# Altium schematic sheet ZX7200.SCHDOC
size 762 x 279 mm; PageSetup: Record=PageOptions|SelectedOnly=False|CenterHorizontal=True|CenterVertical=True|PrintScale=0.95|XCorrection=1.00|YCorrection=1.00|PrintKind=1|BorderSize=5000000|LeftOffset=0|BottomOffset=0|Orientation=1|PaperLength=1000|PaperWidth=1000|Scale=100|PaperSource=7|PrintQuality=-4|MediaType=1|DitherType=10|PaperKind=A4|PrintScaleMode=0
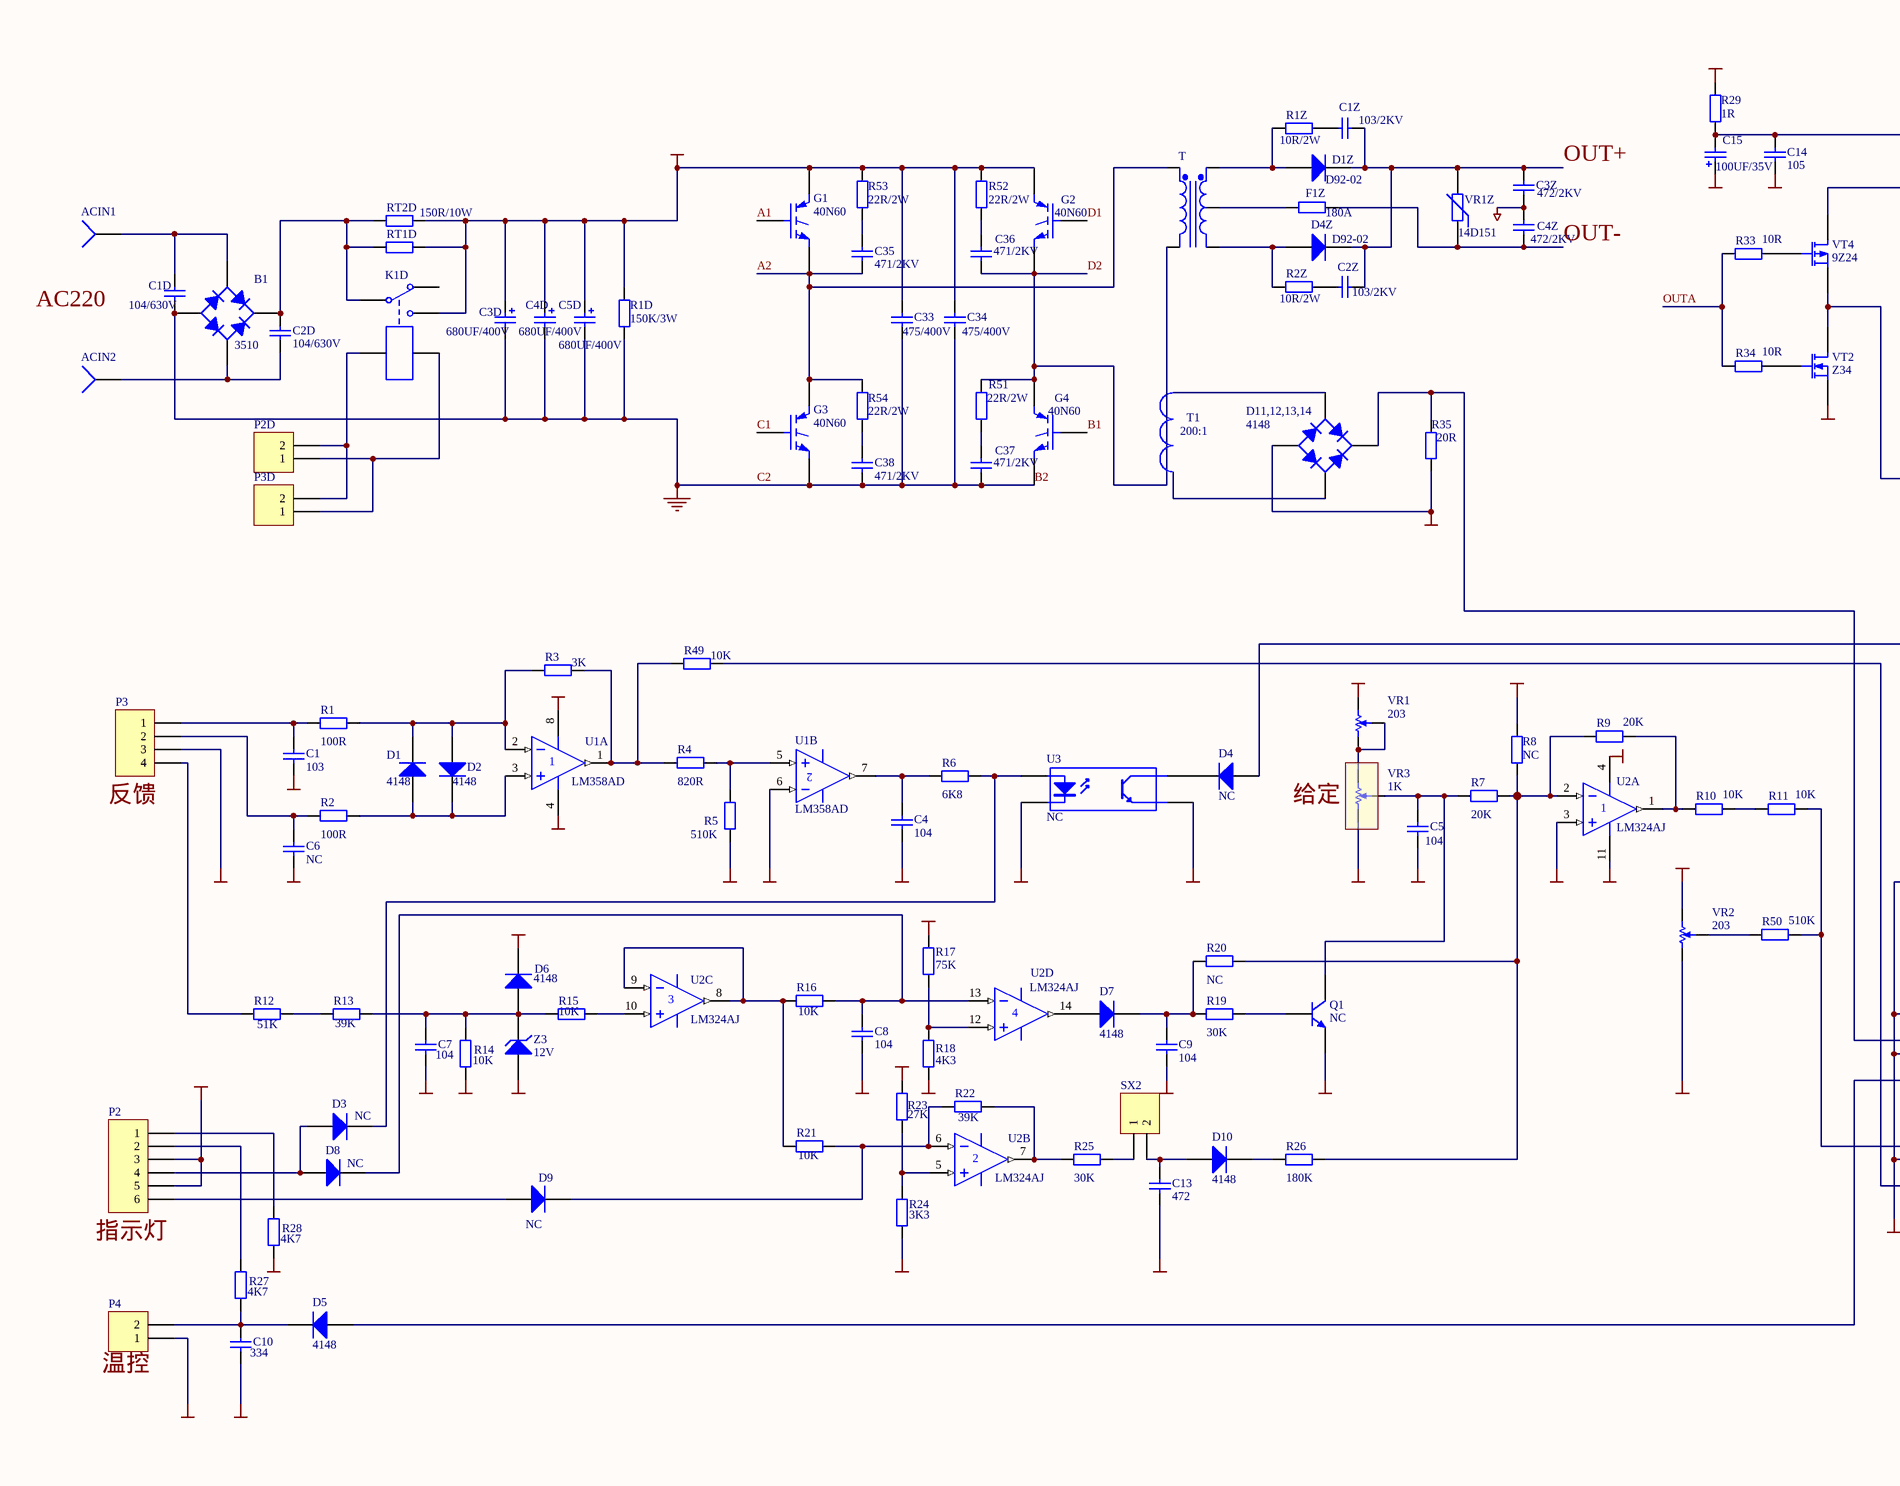
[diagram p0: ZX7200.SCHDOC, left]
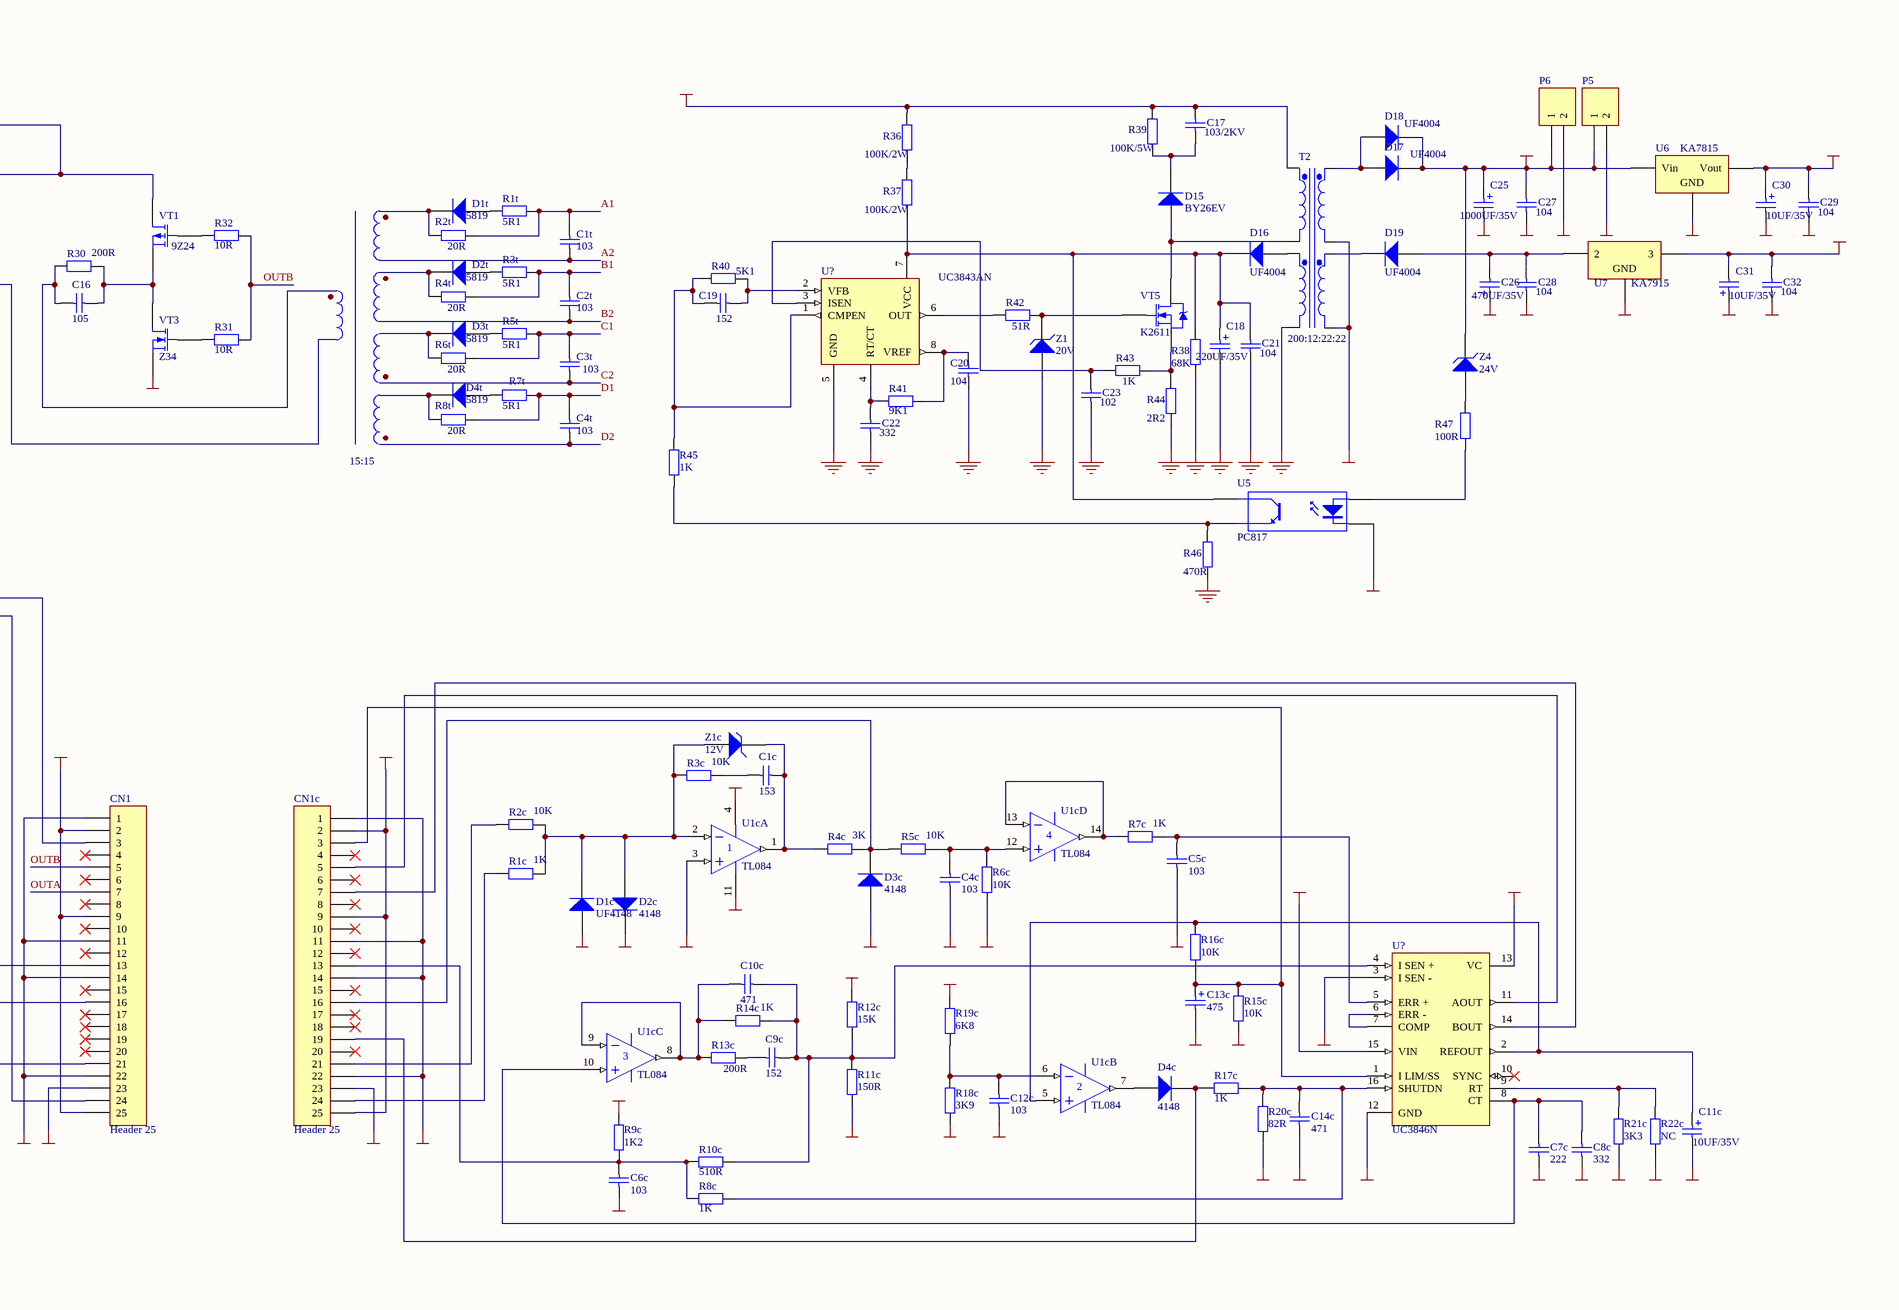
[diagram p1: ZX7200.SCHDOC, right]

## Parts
(Parts that share a designator on the sheet are numbered #1, #2 ... from top to bottom, then left to right.)
ACIN1  (no value)  [PIN1]
ACIN2  (no value)  [PIN1]
B1  3510  [E-BIP-P4/D10]
C1  103  [RAD-0.3]
C1c  153  [RAD-0.3]
C1D  104/630V  [RAD-0.3]
C1t  103  [RAD-0.3]
C1Z  103/2KV  [RAD-0.3]
C2D  104/630V  [RAD-0.3]
C2t  103  [RAD-0.3]
C2Z  103/2KV  [RAD-0.3]
C3D  680UF/400V  [POLAR0.8]
C3t  103  [RAD-0.3]
C3Z  472/2KV  [RAD-0.3]
C4  104  [RAD-0.3]
C4c  103  [RAD-0.3]
C4D  680UF/400V  [POLAR0.8]
C4t  103  [RAD-0.3]
C4Z  472/2KV  [RAD-0.3]
C5  104  [RAD-0.3]
C5c  103  [RAD-0.3]
C5D  680UF/400V  [POLAR0.8]
C6  NC  [RAD-0.3]
C6c  103  [RAD-0.3]
C7  104  [RAD-0.3]
C7c  222  [RAD-0.3]
C8  104  [RAD-0.3]
C8c  332  [RAD-0.3]
C9  104  [RAD-0.3]
C9c  152  [RAD-0.3]
C10  334  [RAD-0.3]
C10c  471  [RAD-0.3]
C11c  10UF/35V  [POLAR0.8]
C12c  103  [RAD-0.3]
C13  472  [RAD-0.3]
C13c  475  [POLAR0.8]
C14  105  [RAD-0.3]
C14c  471  [RAD-0.3]
C15  100UF/35V  [POLAR0.8]
C16  105  [RAD-0.3]
C17  103/2KV  [RAD-0.3]
C18  220UF/35V  [POLAR0.8]
C19  152  [RAD-0.3]
C20  104  [RAD-0.3]
C21  104  [RAD-0.3]
C22  332  [RAD-0.3]
C23  102  [RAD-0.3]
C25  1000UF/35V  [POLAR0.8]
C26  470UF/35V  [POLAR0.8]
C27  104  [RAD-0.3]
C28  104  [RAD-0.3]
C29  104  [RAD-0.3]
C30  10UF/35V  [POLAR0.8]
C31  10UF/35V  [POLAR0.8]
C32  104  [RAD-0.3]
C33  475/400V  [RAD-0.3]
C34  475/400V  [RAD-0.3]
C35  471/2KV  [RAD-0.3]
C36  471/2KV  [RAD-0.3]
C37  471/2KV  [RAD-0.3]
C38  471/2KV  [RAD-0.3]
CN1  Header 25  [HDR1X25]
CN1c  Header 25  [HDR1X25]
D1  4148  [DIO18.84-9.6x5.6]
D1c  UF4148  [DIO18.84-9.6x5.6]
D1t  5819  [DIO18.84-9.6x5.6]
D1Z  D92-02  [DIO18.84-9.6x5.6]
D2  4148  [DIO18.84-9.6x5.6]
D2c  4148  [DIO18.84-9.6x5.6]
D2t  5819  [DIO18.84-9.6x5.6]
D3  NC  [DIO18.84-9.6x5.6]
D3c  4148  [DIO18.84-9.6x5.6]
D3t  5819  [DIO18.84-9.6x5.6]
D4  NC  [DIO18.84-9.6x5.6]
D4c  4148  [DIO18.84-9.6x5.6]
D4t  5819  [DIO18.84-9.6x5.6]
D4Z  D92-02  [DIO18.84-9.6x5.6]
D5  4148  [DIO18.84-9.6x5.6]
D6  4148  [DIO18.84-9.6x5.6]
D7  4148  [DIO18.84-9.6x5.6]
D8  NC  [DIO18.84-9.6x5.6]
D9  NC  [DIO18.84-9.6x5.6]
D10  4148  [DIO18.84-9.6x5.6]
D11,12,13,14  4148  [E-BIP-P4/D10]
D15  BY26EV  [DIO18.84-9.6x5.6]
D16  UF4004  [DIO18.84-9.6x5.6]
D17  UF4004  [DIO18.84-9.6x5.6]
D18  UF4004  [DIO18.84-9.6x5.6]
D19  UF4004  [DIO18.84-9.6x5.6]
F1Z  180A  [AXIAL-0.4]
G1  40N60  [SFM-F3/Y2.3]
G2  40N60  [SFM-F3/Y2.3]
G3  40N60  [SFM-F3/Y2.3]
G4  40N60  [SFM-F3/Y2.3]
K1D  (no value)  [DIP-P5/X1.65]
P2  (no value)  [HDR1X6H]
P2D  (no value)  [HDR1X2]
P3  (no value)  [HDR1X4]
P3D  (no value)  [HDR1X2]
P4  (no value)  [HDR1X2]
P5  (no value)  [HDR1X2]
P6  (no value)  [HDR1X2]
Q1  NC  [BCY-W3/E4]
R1  100R  [AXIAL-0.4]
R1c  1K  [AXIAL-0.4]
R1D  150K/3W  [AXIAL-0.4]
R1t  5R1  [AXIAL-0.4]
R1Z  10R/2W  [AXIAL-0.4]
R2  100R  [AXIAL-0.4]
R2c  10K  [AXIAL-0.4]
R2t  20R  [AXIAL-0.4]
R2Z  10R/2W  [AXIAL-0.4]
R3  3K  [AXIAL-0.4]
R3c  10K  [AXIAL-0.4]
R3t  5R1  [AXIAL-0.4]
R4  820R  [AXIAL-0.4]
R4c  3K  [AXIAL-0.4]
R4t  20R  [AXIAL-0.4]
R5  510K  [AXIAL-0.4]
R5c  10K  [AXIAL-0.4]
R5t  5R1  [AXIAL-0.4]
R6  6K8  [AXIAL-0.4]
R6c  10K  [AXIAL-0.4]
R6t  20R  [AXIAL-0.4]
R7  20K  [AXIAL-0.4]
R7c  1K  [AXIAL-0.4]
R7t  5R1  [AXIAL-0.4]
R8  NC  [AXIAL-0.4]
R8c  1K  [AXIAL-0.4]
R8t  20R  [AXIAL-0.4]
R9  20K  [AXIAL-0.4]
R9c  1K2  [AXIAL-0.4]
R10  10K  [AXIAL-0.4]
R10c  510R  [AXIAL-0.4]
R11  10K  [AXIAL-0.4]
R11c  150R  [AXIAL-0.4]
R12  51K  [AXIAL-0.4]
R12c  15K  [AXIAL-0.4]
R13  39K  [AXIAL-0.4]
R13c  200R  [AXIAL-0.4]
R14  10K  [AXIAL-0.4]
R14c  1K  [AXIAL-0.4]
R15  10K  [AXIAL-0.4]
R15c  10K  [AXIAL-0.4]
R16  10K  [AXIAL-0.4]
R16c  10K  [AXIAL-0.4]
R17  75K  [AXIAL-0.4]
R17c  1K  [AXIAL-0.4]
R18  4K3  [AXIAL-0.4]
R18c  3K9  [AXIAL-0.4]
R19  30K  [AXIAL-0.4]
R19c  6K8  [AXIAL-0.4]
R20  NC  [AXIAL-0.4]
R20c  82R  [AXIAL-0.4]
R21  10K  [AXIAL-0.4]
R21c  3K3  [AXIAL-0.4]
R22  39K  [AXIAL-0.4]
R22c  NC  [AXIAL-0.4]
R23  27K  [AXIAL-0.4]
R24  3K3  [AXIAL-0.4]
R25  30K  [AXIAL-0.4]
R26  180K  [AXIAL-0.4]
R27  4K7  [AXIAL-0.4]
R28  4K7  [AXIAL-0.4]
R29  1R  [AXIAL-0.4]
R30  200R  [AXIAL-0.4]
R31  10R  [AXIAL-0.4]
R32  10R  [AXIAL-0.4]
R33  10R  [AXIAL-0.4]
R34  10R  [AXIAL-0.4]
R35  20R  [AXIAL-0.4]
R36  100K/2W  [AXIAL-0.4]
R37  100K/2W  [AXIAL-0.4]
R38  68K  [AXIAL-0.4]
R39  100K/5W  [AXIAL-0.4]
R40  5K1  [AXIAL-0.4]
R41  9K1  [AXIAL-0.4]
R42  51R  [AXIAL-0.4]
R43  1K  [AXIAL-0.4]
R44  2R2  [AXIAL-0.4]
R45  1K  [AXIAL-0.4]
R46  470R  [AXIAL-0.4]
R47  100R  [AXIAL-0.4]
R49  10K  [AXIAL-0.4]
R50  510K  [AXIAL-0.4]
R51  22R/2W  [AXIAL-0.4]
R52  22R/2W  [AXIAL-0.4]
R53  22R/2W  [AXIAL-0.4]
R54  22R/2W  [AXIAL-0.4]
RT1D  (no value)  [AXIAL-0.4]
RT2D  150R/10W  [AXIAL-0.4]
SX2  (no value)  [HDR1X2]
T  (no value)  [TRF_5]
T2  200:12:22:22  [TRF_8]
U1  LM358AD  [D008]  (parts A,B of 2)
U1c  TL084  [J014]  (parts A,B,C,D of 4)
U2  LM324AJ  [J014]  (parts A,B,C,D of 4)
U3  NC  [DIP-4]
U5  PC817  [DIP-4]
U6  KA7815  [SIP-G3/Y2]
U7  KA7915  [SIP-G3/Y2]
U?#1  UC3843AN  [626-05]
U?#2  UC3846N  [N016]
VR1  203  [POT4MM-2]
VR1Z  14D151  [R2012-0805]
VR2  203  [POT4MM-2]
VR3  1K  [POT4MM-2]
VT1  9Z24  [BCY-W3/B.8]
VT2  Z34  [BCY-W3/B.8]
VT3  Z34  [BCY-W3/B.8]
VT4  9Z24  [BCY-W3/B.8]
VT5  K2611  [SFM-T3/A4.7V]
Z1  20V  [DIODE-0.7]
Z1c  12V  [DIODE-0.7]
Z3  12V  [DIODE-0.7]
Z4  24V  [DIODE-0.7]

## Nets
+15V: C29.2 C30.1 CN1.2 CN1.9 CN1.25 CN1c.2 CN1c.9 CN1c.25 D6.2(K) P2.3 P2.5 R8.2 R9c.1 R17.1 R19c.2 R23.1 R29.2 U1.8(V+) U1c.4(V+) U2.4(V+) U6.3(Vout) U?#2.13(VC) U?#2.15(VIN) VR1.CW(+)
+24V: C25.1 C27.2 D17.2(K) D18.2(K) P5.1 P6.1 U6.1(Vin) Z4.2(K)
+310V: C3D.1 C4D.1 C5D.1 C17.2 C33.2 C34.2 G1.2(C) G2.2(C) K1D.3 R1D.2 R36.1 R39.1 R52.2 R53.2 RT1D.2 RT2D.2 T2.1(Pri1+)
-15V: C31.2 C32.2 CN1.23 CN1c.23 R5.2 R12c.2 U1.4(V-) U1c.11(V-) U2.11(V-) U7.3 VR2.CW(+)
B2: B1.1(A) C1D.1 C2t.1 C3D.2 C3t.1 C3Z.2 C4D.2 C4Z.1 C5D.2 C18.2 C20.1 C21.1 C22.1 C23.1 C33.1 C34.1 C37.1 C38.1 G3.3(E) G4.3(E) R1D.1 R38.2 R44.2 R46.2 T2.4(Pri2-) U?#1.5(GND) Z1.1(A)  [also labelled C2, GND]
NetC1_1: C1.1 C4.1 C4c.2 C5.2 C5c.2 C6.1 C6c.2 C7.1 C7c.2 C8.1 C8c.2 C9.2 C10.1 C11c.2 C12c.2 C13.2 C13c.2 C14.2 C14c.2 C15.1 C25.2 C26.1 C27.1 C28.1 C29.1 C30.2 C31.1 C32.1 CN1.1 CN1.11 CN1.14 CN1.22 CN1c.1 CN1c.11 CN1c.14 CN1c.22 D1c.1(A) D2c.2(K) D3c.1(A) D11,12,13,14.1(A) P3.3 P4.1 P5.2 P6.2 Q1.1(E) R6c.1 R11c.1 R14.2 R15c.2 R18.2 R18c.1 R20c.2 R21c.2 R22c.2 R24.2 R28.2 R35.1 T2.6(Sec1-) T2.8(Sec2-) U1.6(IN-) U1c.3(IN+) U2.3(IN+) U3.2(K) U3.4(E) U5.2(K) U6.2(GND) U7.2 U?#2.3(I_SEN_-) U?#2.12(GND) VR2.CCW(-) VR3.CCW(-) VT2.3(S) VT3.3(S) Z3.1(A)
A1: C1t.2 G1.1(G) R1t.2 R2t.2
A2: C1t.1 C35.1 G1.3(E) G3.2(C) R54.2 T.1(Pri+)
B1: C2t.2 G4.1(G) R3t.2 R4t.2
C1: C3t.2 G3.1(G) R5t.2 R6t.2
D1: C4t.2 G2.1(G) R7t.2 R8t.2
D2: C4t.1 C36.1 G2.3(E) G4.2(C) R51.2 T.2(Pri-)
OUT+: C1Z.1 C2Z.1 C3Z.1 D1Z.2(K) D4Z.2(K) VR1Z.2
OUT-: C4Z.2 F1Z.1 VR1Z.1
OUTA: CN1.7 R33.1 R34.1
OUTB: CN1.5 R31.1 R32.1
NetACIN1_1: ACIN1.1 B1.2(C) C1D.2
NetACIN2_1: ACIN2.1 B1.4(C) C2D.1
NetB1_3: B1.3(K) C2D.2 K1D.1 RT1D.1 RT2D.1
NetC1_2: C1.2 P3.1 R1.2
NetC1c_1: C1c.1 R4c.1 U1c.1(OUT) Z1c.2(K)
NetC1c_2: C1c.2 R3c.2
NetC1Z_2: C1Z.2 R1Z.1
NetC2Z_2: C2Z.2 R2Z.1
NetC4_2: C4.2 R6.1 U1.7(OUT)
NetC4c_1: C4c.1 R5c.2 R6c.2 U1c.12(IN+)
NetC5_1: C5.1 Q1.3(C) R7.1 VR3.W
NetC5c_1: C5c.1 R7c.2 U?#2.5(ERR_+)
NetC6_2: C6.2 P3.2 R2.2
NetC6c_1: C6c.1 CN1c.13 R8c.2 R9c.2 R10c.2
NetC7_2: C7.2 D6.1(A) R13.1 R14.1 R15.2 Z3.2(K)
NetC7c_1: C7c.1 C8c.1 U1c.10(IN+) U?#2.8(CT)
NetC8_2: C8.2 D8.2(K) R16.1 U2.13(IN-)
NetC9_1: C9.1 D7.2(K) R19.1 R20.1
NetC9c_1: C9c.1 R13c.2
NetC9c_2: C9c.2 C10c.2 R10c.1 R11c.2 R12c.1 R14c.2 U?#2.4(I_SEN_+)
NetC10_2: C10.2 D5.2(K) P4.2 R27.2
NetC10c_1: C10c.1 R13c.1 R14c.1 U1c.8(OUT) U1c.9(IN-)
NetC11c_1: C11c.1 R16c.2 U1c.5(IN+) U?#2.2(REFOUT)
NetC12c_1: C12c.1 R18c.2 R19c.1 U1c.6(IN-)
NetC13_1: C13.1 D10.1(A) SX2.2
NetC13c_1: C13c.1 CN1c.3 R15c.1 R16c.1 U?#2.1(I_LIM/SS)
NetC14_1: C14.1 C15.2 R29.1 VT1.1(D) VT4.1(D)
NetC14c_1: C14c.1 R8c.1 R17c.1 R20c.1 U?#2.16(SHUTDN)
NetC16_1: C16.1 R30.1
NetC16_2: C16.2 R30.2 VT1.3(S) VT3.1(D)
NetC17_1: C17.1 D15.2(K) R39.2
NetC18_1: C18.1 C21.2 D16.2(K) R37.2 R38.1 U5.3(C) U?#1.7(VCC)
NetC19_1: C19.1 R40.2 U?#1.2(VFB)
NetC19_2: C19.2 R40.1 R45.2 U?#1.1(CMPEN)
NetC20_2: C20.2 R41.1 U?#1.8(VREF)
NetC22_2: C22.2 R41.2 U?#1.4(RT/CT)
NetC23_2: C23.2 R43.1 U?#1.3(ISEN)
NetC26_2: C26.2 C28.2 D19.1(A) U7.1(2)
NetC35_2: C35.2 R53.1
NetC36_2: C36.2 R52.1
NetC37_2: C37.2 R51.1
NetC38_2: C38.2 R54.1
NetCN1_3: CN1.3 D4.1(A)
NetCN1_13: CN1.13 D11,12,13,14.3(K) R35.2
NetCN1_16: CN1.16 D5.1(A)
NetCN1_21: CN1.21 R11.2 R50.2
NetCN1_24: CN1.24 R49.1
NetCN1c_5: CN1c.5 U?#2.11(AOUT)
NetCN1c_7: CN1c.7 U?#2.14(BOUT)
NetCN1c_16: CN1c.16 D3c.2(K) R4c.2 R5c.1
NetCN1c_19: CN1c.19 D4c.2(K) R17c.2
NetCN1c_21: CN1c.21 R2c.1
NetCN1c_24: CN1c.24 R1c.1
NetD1_1: D1.1(A) D2.2(K) R2.1 U1.3(IN+)
NetD1_2: D1.2(K) D2.1(A) R1.1 R3.2 U1.2(IN-)
NetD1c_2: D1c.2(K) D2c.1(A) R1c.2 R2c.2 R3c.1 U1c.2(IN-) Z1c.1(A)
NetD1t_1: D1t.1(A) R1t.1
NetD1t_2: D1t.2(K) R2t.1
NetD1Z_1: D1Z.1(A) R1Z.2 T.3(Sec+)
NetD2t_1: D2t.1(A) R3t.1
NetD2t_2: D2t.2(K) R4t.1
NetD3_1: D3.1(A) D8.1(A) P2.4
NetD3_2: D3.2(K) R6.2 U3.1(A)
NetD3t_1: D3t.1(A) R5t.1
NetD3t_2: D3t.2(K) R6t.1
NetD4_2: D4.2(K) U3.3(C)
NetD4c_1: D4c.1(A) U1c.7(OUT)
NetD4t_1: D4t.1(A) R7t.1
NetD4t_2: D4t.2(K) R8t.1
NetD4Z_1: D4Z.1(A) R2Z.2 T.5(Sec-)
NetD7_1: D7.1(A) U2.14(OUT)
NetD9_1: D9.1(A) P2.6
NetD9_2: D9.2(K) R21.1 R22.2 U2.6(IN-)
NetD10_2: D10.2(K) R26.1
NetD15_1: D15.1(A) T2.2(Pri1-) VT5.2(D)
NetD16_1: D16.1(A) T2.3(Pri2+)
NetD17_1: D17.1(A) D18.1(A) T2.5(Sec1+)
NetD19_2: D19.2(K) T2.7(Sec2+)
NetF1Z_2: F1Z.2 T.4(SecCT)
NetK1D_4: K1D.4 P2D.2 P3D.2
NetK1D_5: K1D.5 P2D.1 P3D.1
NetP2_1: P2.1 R28.1
NetP2_2: P2.2 R27.1
NetP3_4: P3.4 R12.2
NetQ1_2: Q1.2(B) R19.2
NetR3_1: R3.1 R4.2 R49.2 U1.1(OUT)
NetR4_1: R4.1 R5.1 U1.5(IN+)
NetR7_2: R7.2 R8.1 R9.1 R20.2 R26.2 U2.2(IN-)
NetR7c_1: R7c.1 U1c.13(IN-) U1c.14(OUT)
NetR9_2: R9.2 R10.1 U2.1(OUT)
NetR10_2: R10.2 R11.1
NetR12_1: R12.1 R13.2
NetR15_1: R15.1 U2.10(IN+)
NetR16_2: R16.2 R21.2 U2.8(OUT) U2.9(IN-)
NetR17_2: R17.2 R18.1 U2.12(IN+)
NetR21c_1: R21c.1 R22c.1 U?#2.9(RT)
NetR22_1: R22.1 R25.1 U2.7(OUT)
NetR23_2: R23.2 R24.1 U2.5(IN+)
NetR25_2: R25.2 SX2.1
NetR31_2: R31.2 VT3.2(G)
NetR32_2: R32.2 VT1.2(G)
NetR33_2: R33.2 VT4.2(G)
NetR34_2: R34.2 VT2.2(G)
NetR36_2: R36.2 R37.1
NetR42_1: R42.1 U?#1.6(OUT)
NetR42_2: R42.2 VT5.1(G) Z1.2(K)
NetR43_2: R43.2 R44.1 VT5.3(S)
NetR45_1: R45.1 R46.1 U5.4(E)
NetR47_1: R47.1 Z4.1(A)
NetR47_2: R47.2 U5.1(A)
NetR50_1: R50.1 VR2.W
NetU?#2_6: U?#2.6(ERR_-) U?#2.7(COMP)
NetVR1_CCW: VR1.CCW(-) VR1.W VR3.CW(+)
NetVT2_1: VT2.1(D) VT4.3(S)

Not connected (* = marked no-connect by the designer): CN1 4* 6* 8* 10* 12* 15* 17* 18* 19* 20*; CN1c 4* 6* 8* 10* 12* 15* 17* 18* 20*; D11,12,13,14 2(C) 4(C); K1D 2; U?#2 10(SYNC)*

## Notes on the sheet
- AC220
- 200:1
- T1
- 15:15
- (near P3) 反馈
- 给定
- (near P2) 指示灯
- (near P4) 温控

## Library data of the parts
ACIN1 ACIN2 = Socket
B1 D11,12,13,14 = Bridge1: Full Wave Diode Bridge
C1 C1c C1D C1t C1Z C2D C2t C2Z C3t C3Z C4 C4c C4t C4Z C5 C5c C6 C6c C7 C7c C8 C8c C9 C9c C10 C10c C12c C13 C14 C14c C16 C17 C19-C23 C27-C29 C32-C38 = Cap: Capacitor; Value: 100pF
C3D C4D C5D C11c C13c C15 C18 C25 C26 C30 C31 = Cap Pol2: Polarized Capacitor (Axial); Value: 100pF
CN1 CN1c = Header 25: Header, 25-Pin
D1 D1c D1t D1Z D2 D2c D2t D3 D3c D3t D4 D4c D4t D4Z D5-D10 D15-D19 = Diode 1N5401: 3 Amp General Purpose Rectifier
F1Z R1 R1D R1t R1Z R2 R2c R2t R2Z R3 R3c R3t R4 R4c R4t R5 R5c R5t R6 R6c R6t R7 R7t R8 R8t R9 R9c R10 R10c R11 R11c R12 R12c R13 R13c R14 R15 R15c R16 R16c R17 R18 R18c R19 R19c R20 R20c R21 R21c R22 R22c R23-R42 R44 R46 R47 R49-R54 RT1D RT2D = Res2: Resistor; Value: 1K
G1-G4 = IGBT-N: Insulated Gate Bipolar Transistor (N-Channel)
K1D = Relay-SPDT: Single-Pole Dual-Throw Relay
P2 = Header 6H: Header, 6-Pin, Right Angle
P2D P3D P4-P6 SX2 = Header 2: Header, 2-Pin
P3 = Header 4: Header, 4-Pin
Q1 = 2N3904: NPN General Purpose Amplifier
R1c R7c R8c R14c R17c R43 R45 = Res2: Resistor
T = Trans CT: Center-Tapped Transformer (Coupled Inductor Model)
T2 = Trans BB: Buck-boost Transformer (Ideal)
U1 = LM358AD: Dual Operational Amplifier
U1c U2 = LM324AJ: Quadruple Operational Amplifier
U3 U5 = Optoisolator1: Optoisolator
U6 U7 = Volt Reg: Voltage Regulator
U?#1 = UC3843AN: High-Performance Current Mode Controller
U?#2 = UC3846N: Current-Mode PWM Controller
VR1-VR3 = RPot SM: Square Trimming Potentiometer
VR1Z = Res Varistor: Varistor (Voltage-Sensitive Resistor)
VT1 VT4 = MOSFET-P: P-Channel MOSFET
VT2 VT3 = MOSFET-N: N-Channel MOSFET
VT5 = NMOS-2: N-Channel Power MOSFET; Note: Pin 2 is electrically connected to pin 4.
Z1 Z1c Z3 Z4 = D Zener: Zener Diode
